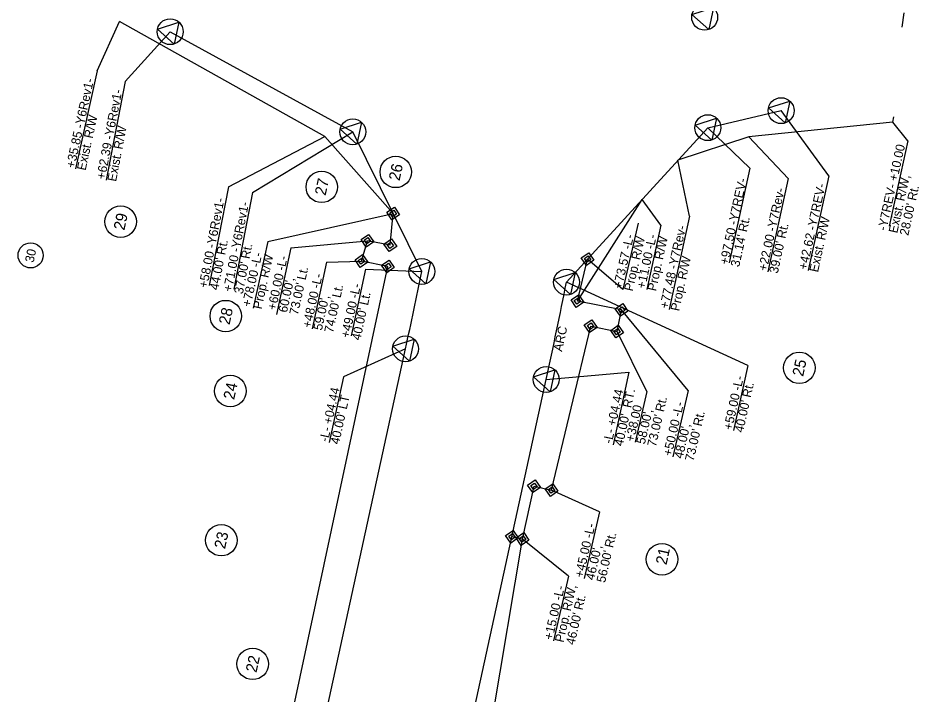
# Model space of a CAD drawing. Extents: x 1610947 to 1617684, y 899814 to 904658.
# Drawn here: x 1616339 to 1616840, y 901302 to 901678 of the extents above; entities that cross this region are included whole.
import ezdxf

# ---------------------------------------------------------------- set-up
doc = ezdxf.new("R2010")
doc.units = 0
for name, color, linetype in [('Prop Conc 1ft 6in Curb and Gutter', 7, 'Continuous'), ('Prop EOT Dash', 7, 'Continuous'), ('Prop Hatching', 7, 'Continuous'), ('Prop Horizontal Alignment Direction Label', 7, 'Continuous'), ('Prop Horizontal Alignment Tick Label', 7, 'Continuous'), ('Prop ROW Marker CELL', 7, 'Continuous'), ('Prop ROW RW Lines', 7, 'Continuous'), ('Prop ROW Station Offsets', 7, 'Continuous'), ('Scratch_Level_3', 7, 'Continuous')]:
    doc.layers.add(name, color=color, linetype=linetype)

msp = doc.modelspace()

# ---------------------------------------------------------------- linework, layer by layer
at = {"layer": 'Prop Conc 1ft 6in Curb and Gutter'}
for p, q in [((1616383.23, 901649.16), (1616395.67, 901676.43)), ((1616383.23, 901649.16), (1616371.32, 901594.61)), ((1616833.63, 901610.2), (1616825.34, 901620.61)), ((1616456.14, 901584.55), (1616509.82, 901612.53)), ((1616833.63, 901610.2), (1616823.2, 901562.81)), ((1616767.15, 901589.19), (1616755.83, 901537.35)), ((1616456.14, 901584.55), (1616445.56, 901529.73)), ((1616696.35, 901563.36), (1616686.02, 901577.61)), ((1616712.38, 901568.29), (1616701.06, 901516.44)), ((1616696.35, 901563.36), (1616688.52, 901527.48))]:
    msp.add_line(p, q, dxfattribs=at)
for points in [[(1616767.15, 901589.19), (1616745.33, 901612.46)], [(1616712.38, 901568.29), (1616705.92, 901599.38)]]:
    msp.add_lwpolyline(points, dxfattribs=at)
at = {"layer": 'Prop EOT Dash'}
for points in [[(1616544.16, 901570.46), (1616548.37, 901573.33), (1616551.24, 901569.12), (1616547.03, 901566.25)], [(1616545.93, 901570.13), (1616548.04, 901571.56), (1616549.47, 901569.45), (1616547.36, 901568.02)], [(1616529.83, 901555.33), (1616534.04, 901558.2), (1616536.9, 901553.99), (1616532.69, 901551.13)], [(1616531.6, 901555), (1616533.7, 901556.43), (1616535.13, 901554.33), (1616533.03, 901552.89)], [(1616542.58, 901552.8), (1616546.79, 901555.67), (1616549.65, 901551.46), (1616545.44, 901548.59)], [(1616544.35, 901552.47), (1616546.45, 901553.9), (1616547.88, 901551.8), (1616545.78, 901550.36)], [(1616526.54, 901544.05), (1616530.75, 901546.92), (1616533.62, 901542.71), (1616529.41, 901539.85)], [(1616652.15, 901545.11), (1616656.36, 901547.97), (1616659.22, 901543.77), (1616655.01, 901540.9)], [(1616528.31, 901543.72), (1616530.42, 901545.15), (1616531.85, 901543.05), (1616529.75, 901541.61)], [(1616541.25, 901541.07), (1616545.45, 901543.94), (1616548.32, 901539.73), (1616544.11, 901536.87)], [(1616543.01, 901540.74), (1616545.12, 901542.17), (1616546.55, 901540.07), (1616544.45, 901538.63)], [(1616653.92, 901544.77), (1616656.02, 901546.2), (1616657.45, 901544.1), (1616655.35, 901542.67)], [(1616646.52, 901521.81), (1616650.72, 901524.67), (1616653.59, 901520.47), (1616649.38, 901517.6)], [(1616648.28, 901521.47), (1616650.39, 901522.91), (1616651.82, 901520.8), (1616649.72, 901519.37)], [(1616671.02, 901516.86), (1616675.23, 901519.72), (1616678.09, 901515.52), (1616673.89, 901512.65)], [(1616672.79, 901516.52), (1616674.89, 901517.96), (1616676.33, 901515.85), (1616674.22, 901514.42)], [(1616653.87, 901507.84), (1616658.08, 901510.71), (1616660.95, 901506.5), (1616656.74, 901503.64)], [(1616655.64, 901507.51), (1616657.74, 901508.94), (1616659.18, 901506.84), (1616657.07, 901505.4)], [(1616668.56, 901504.82), (1616672.77, 901507.68), (1616675.64, 901503.47), (1616671.43, 901500.61)], [(1616670.33, 901504.48), (1616672.44, 901505.91), (1616673.87, 901503.81), (1616671.76, 901502.38)], [(1616622.4, 901418.86), (1616626.61, 901421.72), (1616629.47, 901417.51), (1616625.27, 901414.65)], [(1616624.17, 901418.52), (1616626.27, 901419.95), (1616627.7, 901417.85), (1616625.6, 901416.42)], [(1616632.17, 901416.73), (1616636.38, 901419.59), (1616639.24, 901415.38), (1616635.04, 901412.52)], [(1616633.94, 901416.39), (1616636.04, 901417.82), (1616637.48, 901415.72), (1616635.37, 901414.29)], [(1616610.15, 901390.82), (1616614.36, 901393.69), (1616617.22, 901389.48), (1616613.02, 901386.61)], [(1616611.92, 901390.49), (1616614.02, 901391.92), (1616615.46, 901389.81), (1616613.35, 901388.38)], [(1616616.01, 901389.54), (1616620.22, 901392.41), (1616623.09, 901388.2), (1616618.88, 901385.34)], [(1616617.78, 901389.21), (1616619.89, 901390.64), (1616621.32, 901388.54), (1616619.22, 901387.1)]]:
    msp.add_lwpolyline(points, close=True, dxfattribs=at)
at = {"layer": 'Prop Hatching'}
for centre, radius in [((1616549.16, 901592.9), 8.75), ((1616508.05, 901584.58), 8.75), ((1616396.28, 901565.27), 8.75), ((1616346.3, 901546.52), 7), ((1616454.71, 901512.77), 8.75), ((1616773.33, 901484.01), 8.75), ((1616457.26, 901471.11), 8.75), ((1616452.2, 901388.19), 8.75), ((1616697.06, 901377.58), 8.75), ((1616469.68, 901319.47), 8.75)]:
    msp.add_circle(centre, radius, dxfattribs=at)
at = {"layer": 'Prop Horizontal Alignment Direction Label'}
for p, q in [((1616546.12, 901552.13), (1616547.7, 901569.79)), ((1616530.08, 901543.38), (1616533.36, 901554.66)), ((1616546.12, 901552.13), (1616533.36, 901554.66)), ((1616544.78, 901540.4), (1616530.08, 901543.38)), ((1616650.05, 901521.14), (1616655.68, 901544.44)), ((1616473.87, 901208.75), (1616544.78, 901540.4)), ((1616674.56, 901516.19), (1616650.05, 901521.14)), ((1616672.1, 901504.14), (1616674.56, 901516.19)), ((1616635.71, 901416.06), (1616657.41, 901507.17)), ((1616657.41, 901507.17), (1616672.1, 901504.14)), ((1616619.55, 901388.87), (1616625.94, 901418.18)), ((1616625.94, 901418.18), (1616635.71, 901416.06)), ((1616619.55, 901388.87), (1616613.69, 901390.15))]:
    msp.add_line(p, q, dxfattribs=at)
at = {"layer": 'Prop Horizontal Alignment Tick Label'}
for p, q in [((1616478.01, 901554.21), (1616547.7, 901569.79)), ((1616683.75, 901564.49), (1616675.25, 901527.54)), ((1616478.01, 901554.21), (1616469.93, 901517.16)), ((1616490.94, 901550.76), (1616533.36, 901554.66)), ((1616490.94, 901550.76), (1616482.85, 901513.71)), ((1616510.7, 901542.76), (1616502.62, 901505.72)), ((1616711.58, 901471.41), (1616674.56, 901516.19)), ((1616688.61, 901470.83), (1616672.1, 901504.14)), ((1616711.58, 901471.41), (1616703.09, 901434.46)), ((1616688.61, 901470.83), (1616682.16, 901442.76)), ((1616662.31, 901403.9), (1616653.82, 901366.95)), ((1616645.05, 901368.14), (1616636.82, 901332.35))]:
    msp.add_line(p, q, dxfattribs=at)
for points in [[(1616510.7, 901542.76), (1616530.08, 901543.38)], [(1616675.25, 901527.54), (1616655.68, 901544.44)], [(1616662.31, 901403.9), (1616635.71, 901416.06)], [(1616645.05, 901368.14), (1616619.55, 901388.87)]]:
    msp.add_lwpolyline(points, dxfattribs=at)
at = {"layer": 'Prop ROW Marker CELL'}
for p, q in [((1616423.84, 901670.83), (1616423.84, 901670.83)), ((1616763.18, 901626.95), (1616763.18, 901626.95)), ((1616722.48, 901617.48), (1616722.48, 901617.48)), ((1616525.29, 901615.15), (1616525.29, 901615.15)), ((1616547.7, 901569.79), (1616547.7, 901569.79)), ((1616533.36, 901554.66), (1616533.36, 901554.66)), ((1616546.12, 901552.13), (1616546.12, 901552.13)), ((1616530.08, 901543.38), (1616530.08, 901543.38)), ((1616655.68, 901544.44), (1616655.68, 901544.44)), ((1616544.78, 901540.4), (1616544.78, 901540.4)), ((1616563.6, 901537.6), (1616563.6, 901537.6)), ((1616644, 901531.66), (1616644, 901531.66)), ((1616650.05, 901521.14), (1616650.05, 901521.14)), ((1616674.56, 901516.19), (1616674.56, 901516.19)), ((1616657.41, 901507.17), (1616657.41, 901507.17)), ((1616672.1, 901504.14), (1616672.1, 901504.14)), ((1616554.56, 901494.57), (1616554.56, 901494.57)), ((1616632.73, 901477.54), (1616632.73, 901477.54)), ((1616625.94, 901418.18), (1616625.94, 901418.18)), ((1616635.71, 901416.06), (1616635.71, 901416.06)), ((1616613.69, 901390.15), (1616613.69, 901390.15)), ((1616619.55, 901388.87), (1616619.55, 901388.87))]:
    msp.add_line(p, q, dxfattribs=at)
for points in [[(1616722.96, 901671.99), (1616713.69, 901680.34), (1616725.55, 901684.21)], [(1616426.06, 901663.97), (1616416.79, 901672.33), (1616428.66, 901676.2)], [(1616765.4, 901620.09), (1616756.14, 901628.44), (1616768, 901632.31)], [(1616724.7, 901610.62), (1616715.43, 901618.97), (1616727.3, 901622.84)], [(1616527.52, 901608.29), (1616518.25, 901616.65), (1616530.11, 901620.52)], [(1616565.82, 901530.73), (1616556.56, 901539.09), (1616568.42, 901542.96)], [(1616646.23, 901524.8), (1616636.96, 901533.16), (1616648.82, 901537.03)], [(1616556.78, 901487.71), (1616547.52, 901496.06), (1616559.38, 901499.93)], [(1616634.95, 901470.68), (1616625.68, 901479.04), (1616637.55, 901482.91)]]:
    msp.add_lwpolyline(points, close=True, dxfattribs=at)
for centre in [(1616720.73, 901678.85), (1616423.84, 901670.83), (1616763.18, 901626.95), (1616525.29, 901615.15), (1616722.48, 901617.48), (1616563.6, 901537.6), (1616644, 901531.66), (1616554.56, 901494.57), (1616632.73, 901477.54)]:
    msp.add_circle(centre, 7.2, dxfattribs=at)
at = {"layer": 'Prop ROW RW Lines'}
for p, q in [((1616423.84, 901670.83), (1616525.29, 901615.15)), ((1616722.48, 901617.48), (1616763.18, 901626.95)), ((1616644, 901531.66), (1616722.48, 901617.48)), ((1616563.6, 901537.6), (1616525.29, 901615.15)), ((1616403.76, 900802.37), (1616554.56, 901494.57)), ((1616493.5, 900838.48), (1616632.73, 901477.54))]:
    msp.add_line(p, q, dxfattribs=at)
msp.add_lwpolyline([(1616554.56, 901494.57), (1616554.56, 901494.57)], dxfattribs=at)
for centre, radius, start, end in [((1613606.79, 902136.33), 3016.82, 347.71756, 348.5528), ((1613695.11, 902117.83), 3006.58, 347.70399, 348.75759)]:
    msp.add_arc(centre, radius, start, end, dxfattribs=at)
at = {"layer": 'Prop ROW Station Offsets'}
for p, q in [((1616398.82, 901643.14), (1616388.23, 901588.33)), ((1616789.67, 901590.66), (1616763.18, 901626.95)), ((1616745.84, 901595.06), (1616722.48, 901617.48)), ((1616469.56, 901581.41), (1616525.29, 901615.15)), ((1616745.84, 901595.06), (1616734.35, 901542.43)), ((1616789.67, 901590.66), (1616778.18, 901538.02)), ((1616469.56, 901581.41), (1616459.2, 901527.76)), ((1616532.38, 901538.93), (1616524.29, 901501.88)), ((1616532.38, 901538.93), (1616563.6, 901537.6)), ((1616744.74, 901485.38), (1616644, 901531.66)), ((1616554.56, 901494.57), (1616520.11, 901478.92)), ((1616632.73, 901477.54), (1616678.62, 901481.51)), ((1616678.62, 901481.51), (1616669.83, 901441.23)), ((1616744.74, 901485.38), (1616736.84, 901449.2)), ((1616520.11, 901478.92), (1616512.16, 901442.49))]:
    msp.add_line(p, q, dxfattribs=at)
msp.add_lwpolyline([(1616398.82, 901643.14), (1616423.84, 901670.83)], dxfattribs=at)
at = {"layer": 'Scratch_Level_3'}
for p, q in [((1616831.42, 901681.38), (1616830.23, 901673.44)), ((1616509.82, 901612.53), (1616395.67, 901676.43)), ((1616825.34, 901620.61), (1616825.78, 901623.58)), ((1616825.34, 901620.61), (1616745.33, 901612.46)), ((1616547.7, 901569.79), (1616509.82, 901612.53)), ((1616745.33, 901612.46), (1616705.92, 901599.38)), ((1616650.05, 901521.14), (1616686.02, 901577.61)), ((1616592.67, 901227.91), (1616619.55, 901388.87))]:
    msp.add_line(p, q, dxfattribs=at)

# ---------------------------------------------------------------- texts
at = {"layer": 'Prop Conc 1ft 6in Curb and Gutter'}
for s, rotation, p in [('+35.85 -Y6Rev1-', 77.6862, (1616370.71, 901594.75)), ('Exist. R/W', 77.6862, (1616376.82, 901593.41)), ('-Y7REV- +10.00', 77.5866, (1616821.6, 901559.89)), ('Exist. R/W,', 77.5866, (1616827.71, 901558.55)), ('+22.00 -Y7Rev-', 77.6862, (1616755.22, 901537.48)), ("28.00' Rt.", 77.5866, (1616833.81, 901557.2)), ('+58.00 -Y6Rev1-', 79.0727, (1616444.42, 901528.11)), ('+77.48 -Y7Rev-', 77.6862, (1616700.45, 901516.57)), ("39.00' Rt.", 77.6862, (1616761.32, 901536.15)), ('+11.00 -L-', 77.6862, (1616687.63, 901527.67)), ('Prop. R/W', 77.6862, (1616693.73, 901526.34)), ("44.00' Rt.", 79.0727, (1616450.56, 901526.92)), ('Prop. R/W', 77.6862, (1616706.55, 901515.24))]:
    msp.add_text(s, height=5, rotation=rotation, dxfattribs=at).set_placement(p)
at = {"layer": 'Prop Hatching'}
for s, height, rotation, p in [('26', 6.25, 77.7167, (1616551.21, 901587.62)), ('27', 6.25, 77.7167, (1616510.13, 901579.44)), ('29', 6.25, 77.7167, (1616398.36, 901560.14)), ('30', 5, 78.0945, (1616347.95, 901542.22)), ('28', 6.25, 77.7167, (1616456.79, 901507.64)), ('25', 6.25, 77.7167, (1616775.41, 901478.88)), ('24', 6.25, 77.7167, (1616459.34, 901465.97)), ('23', 6.25, 77.7167, (1616454.28, 901383.06)), ('21', 6.25, 77.7167, (1616699.52, 901374.18)), ('22', 6.25, 77.7167, (1616471.76, 901314.33))]:
    msp.add_text(s, height=height, rotation=rotation, dxfattribs=at).set_placement(p)
at = {"layer": 'Prop Horizontal Alignment Tick Label'}
for s, rotation, p in [('+73.57 -L-', 77.0556, (1616674.64, 901527.68)), ('Prop. R/W', 77.0556, (1616680.74, 901526.28)), ('+78.00 -L-', 77.6862, (1616468.48, 901517.63)), ('Prop. R/W', 77.6862, (1616474.58, 901516.3)), ('+60.00 -L-', 77.6862, (1616482.57, 901515.75)), ("73.00' Lt.", 77.6862, (1616494.78, 901513.08)), ("60.00',", 77.6862, (1616488.68, 901514.41)), ('+48.00 -L-', 77.6862, (1616502.01, 901505.85)), ("74.00' Lt.", 77.6862, (1616514.22, 901503.18)), ("59.00',", 77.6862, (1616508.11, 901504.52)), ("73.00' Rt.", 77.0556, (1616693.58, 901439.83)), ('+38.00', 77.0556, (1616681.4, 901442.64)), ('+50.00 -L-', 77.0556, (1616702.39, 901434.62)), ("58.00',", 77.0556, (1616687.49, 901441.24)), ("73.00' Rt.", 77.0556, (1616714.57, 901431.82)), ("48.00',", 77.0556, (1616708.48, 901433.22)), ('+45.00 -L-', 77.0556, (1616653.21, 901367.09)), ("56.00' Rt.", 77.0556, (1616665.39, 901364.29)), ("46.00',", 77.0556, (1616659.3, 901365.69)), ('+15.00 -L-', 77.0556, (1616636.21, 901332.49)), ('Prop. R/W,', 77.0556, (1616642.3, 901331.09)), ("46.00' Rt.", 77.0556, (1616648.39, 901329.69))]:
    msp.add_text(s, height=5, rotation=rotation, dxfattribs=at).set_placement(p)
at = {"layer": 'Prop ROW Station Offsets'}
for s, rotation, p in [('+62.39 -Y6Rev1-', 79.0727, (1616387.62, 901588.45)), ('Exist. R/W', 79.0727, (1616393.76, 901587.26)), ('+97.50 -Y7REV-', 77.6862, (1616733.8, 901541.1)), ('+42.62 -Y7REV-', 77.6862, (1616777.57, 901538.16)), ('+71.00 -Y6Rev1-', 79.0727, (1616458.02, 901525.94)), ("31.14' Rt.", 77.6862, (1616739.91, 901539.77)), ('Exist. R/W', 77.6862, (1616783.68, 901536.82)), ("37.00' Rt.", 79.0727, (1616464.15, 901524.76)), ('+49.00 -L-', 77.6862, (1616523.33, 901500.33)), ("40.00' Lt.", 77.6862, (1616529.44, 901498.99)), ('ARC', 77.6862, (1616641.49, 901492.75)), ('+59.00 -L-', 77.6862, (1616735.97, 901449.09)), ('-L- +04.44', 77.6862, (1616511.52, 901442.56)), ('-L- +04.44', 77.6862, (1616669.16, 901441.55)), ("40.00'  RT.", 77.6862, (1616675.26, 901440.22)), ("40.00' Rt.", 77.6862, (1616742.08, 901447.76)), ("40.00' LT", 77.6862, (1616517.63, 901441.23))]:
    msp.add_text(s, height=5, rotation=rotation, dxfattribs=at).set_placement(p)

doc.saveas('drawing.dxf')
